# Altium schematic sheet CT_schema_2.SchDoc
size 289 x 230 mm
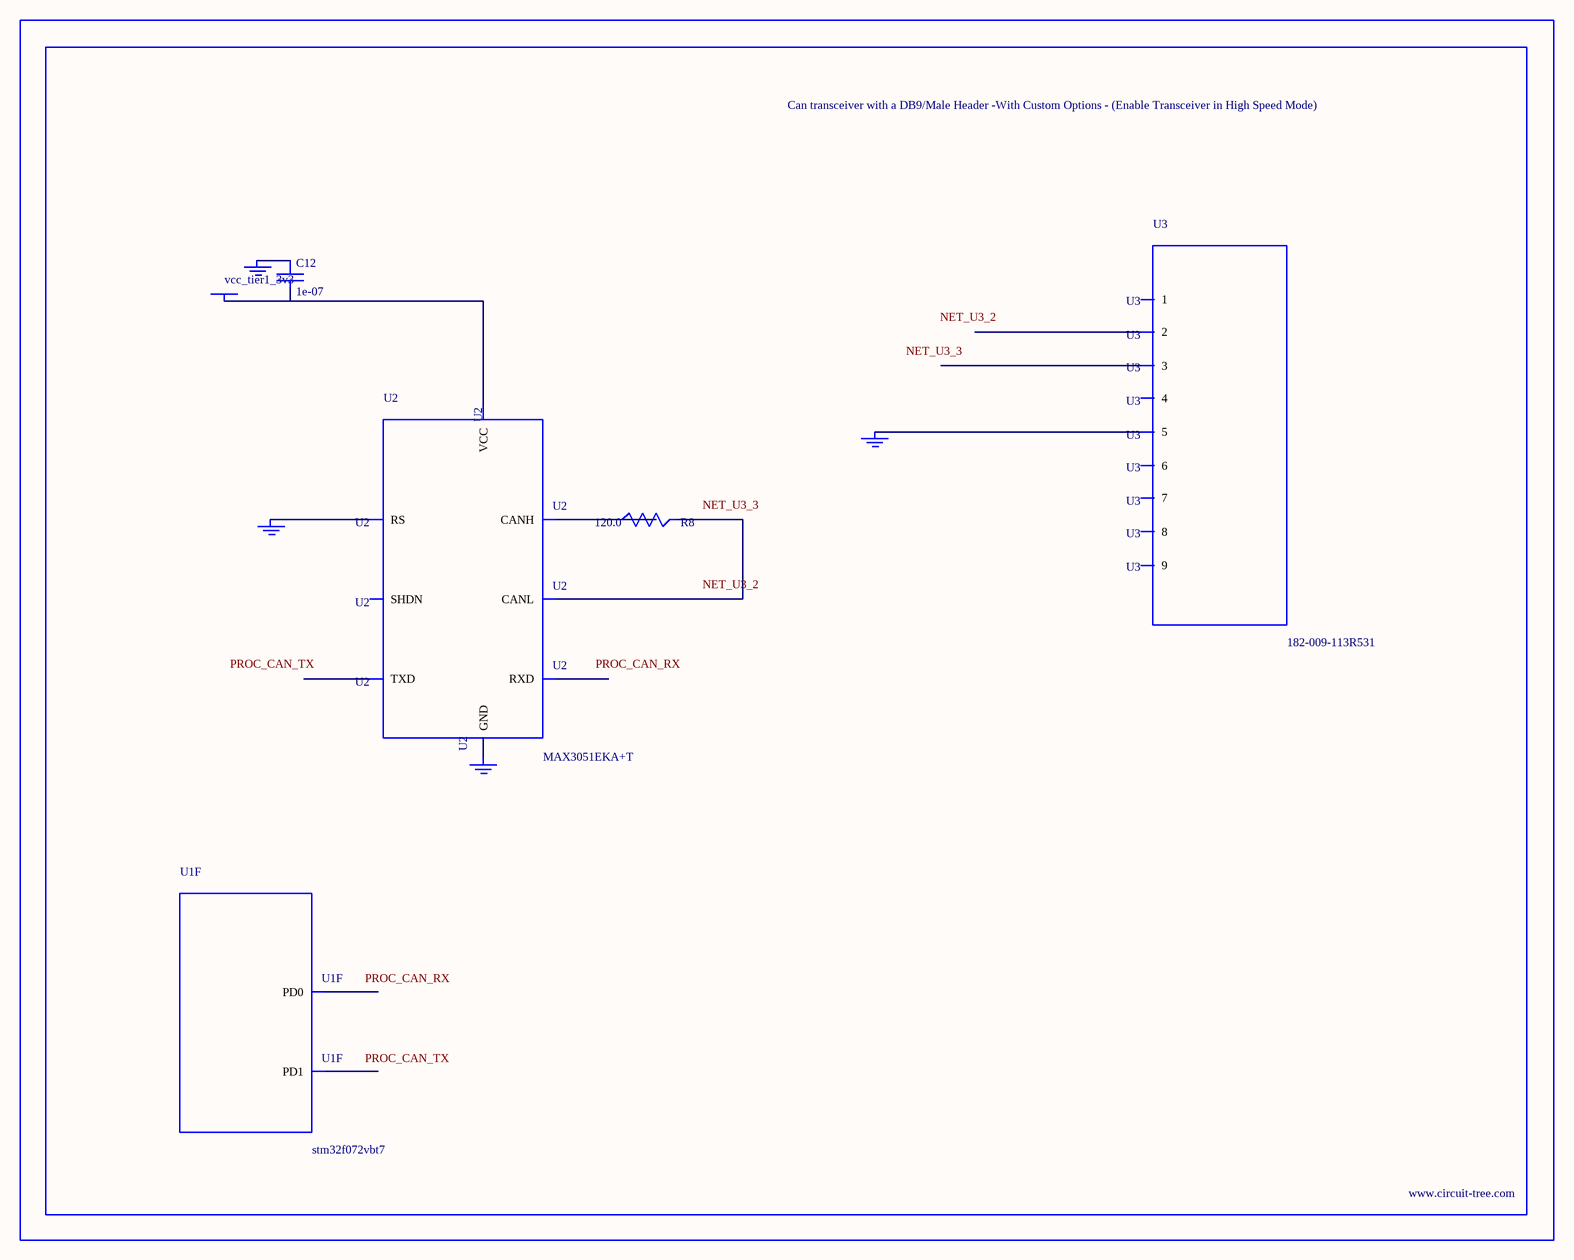
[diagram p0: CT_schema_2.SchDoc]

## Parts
BORDER1  (no value)
C12  1e-07  [C0402]
GND_INSTANCE_1_0  (no value)
GND_INSTANCE_1_1  (no value)
GND_INSTANCE_1_2  (no value)
GND_INSTANCE_1_3  (no value)
POWER_INSTANCE_1_0  vcc_tier1_3v3
R8  120.0  [R0603]
U1  stm32f072vbt7  [LQFP100]  (part F of 10)
U2  MAX3051EKA+T  [SOT-23-8]
U3  182-009-113R531  [182-009-MALE]

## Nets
NetC12_1: C12.1 GND_INSTANCE_1_0.0(GND)
NetC12_2: C12.2 POWER_INSTANCE_1_0.0(PWR) U2.3(VCC)
NetGND_INSTANCE_1_1_0: GND_INSTANCE_1_1.0(GND) U2.8(RS)
NetGND_INSTANCE_1_2_0: GND_INSTANCE_1_2.0(GND) U2.2(GND)
NetGND_INSTANCE_1_3_0: GND_INSTANCE_1_3.0(GND) U3.5
NetR8_1: R8.1 U2.7(CANH)
NetR8_2: R8.2 U2.6(CANL)

Not connected (* = marked no-connect by the designer): U1 81(PD0) 82(PD1); U2 1(TXD) 4(RXD) 5(SHDN); U3 1 2 3 4 6 7 8 9

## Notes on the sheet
- Labels drawn without touching a wire or pin: NET_U3_2, NET_U3_3, PROC_CAN_RX, PROC_CAN_TX

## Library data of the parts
BORDER1 = BORDER_PAGE1
C12 = C0402C104K3RACTU
GND_INSTANCE_1_0-GND_INSTANCE_1_3 = GND
POWER_INSTANCE_1_0 = PWR
R8 = RC0603JR-07120RL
